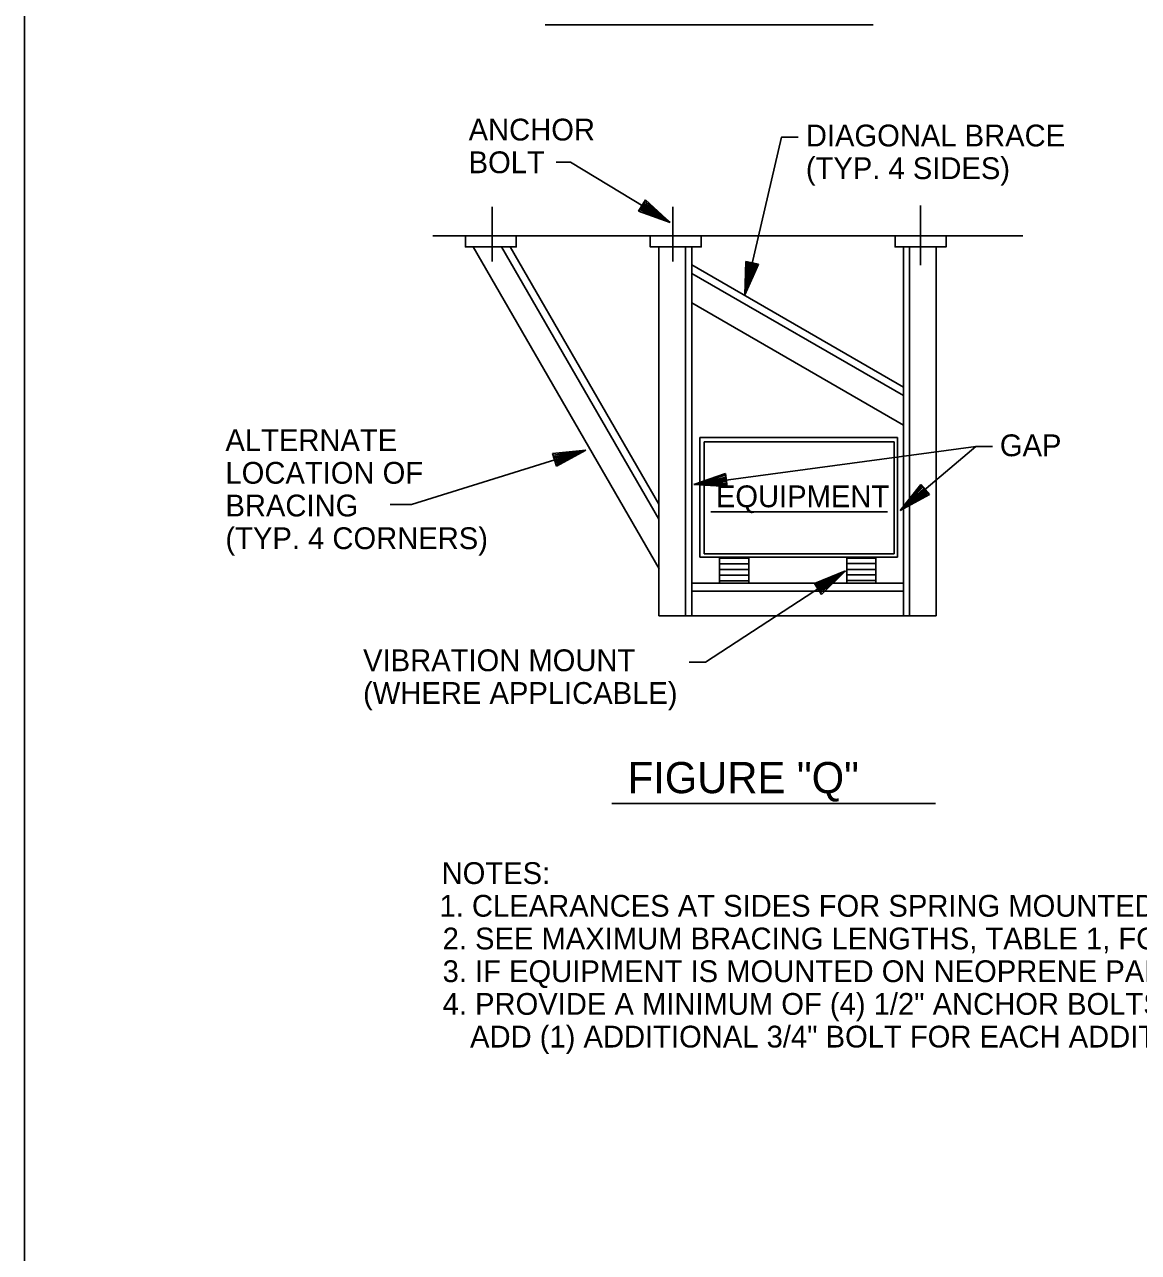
# Model space of a CAD drawing. Extents: x 10040.55 to 10045.84, y 10033.26 to 10035.76.
# Drawn here: x 10042.235 to 10042.746, y 10034.627 to 10035.19 of the extents above; entities that cross this region are included whole.
import ezdxf

# ---------------------------------------------------------------- set-up
doc = ezdxf.new("R2010")
doc.units = 0
doc.layers.add('Level 2', color=7, linetype='Continuous')

msp = doc.modelspace()

# ---------------------------------------------------------------- linework, layer by layer
at = {"layer": 'Level 2'}
for p, q in [((10042.2348, 10035.71385), (10042.2348, 10033.29719)), ((10042.47355, 10035.18978), (10042.62399, 10035.18978)), ((10042.44921, 10035.08122), (10042.44921, 10035.10631)), ((10042.51636, 10035.10443), (10042.5195, 10035.10957)), ((10042.53079, 10035.09918), (10042.51676, 10035.10508)), ((10042.53079, 10035.09918), (10042.51718, 10035.10581)), ((10042.53079, 10035.09918), (10042.51754, 10035.10638)), ((10042.51791, 10035.10698), (10042.53079, 10035.09918)), ((10042.53079, 10035.09918), (10042.5183, 10035.10761)), ((10042.53079, 10035.09918), (10042.51868, 10035.10826)), ((10042.53079, 10035.09918), (10042.51906, 10035.10888)), ((10042.5195, 10035.10957), (10042.53079, 10035.09918)), ((10042.53207, 10035.08122), (10042.53207, 10035.10631)), ((10042.64569, 10035.07959), (10042.64569, 10035.10702)), ((10042.51636, 10035.10443), (10042.53079, 10035.09918)), ((10042.42202, 10035.09301), (10042.69251, 10035.09301)), ((10042.52575, 10034.94035), (10042.44052, 10035.08798)), ((10042.52568, 10034.96305), (10042.45355, 10035.08798)), ((10042.52568, 10034.96995), (10042.45753, 10035.08798)), ((10042.52568, 10034.91869), (10042.52568, 10035.08798)), ((10042.53794, 10035.08798), (10042.53794, 10034.91869)), ((10042.54078, 10034.91869), (10042.54078, 10035.08798)), ((10042.63777, 10035.08798), (10042.63777, 10034.91869)), ((10042.6406, 10034.91869), (10042.6406, 10035.08798)), ((10042.65288, 10035.08798), (10042.65288, 10034.91869)), ((10042.63777, 10035.02368), (10042.54078, 10035.07968)), ((10042.56553, 10035.08135), (10042.56504, 10035.06601)), ((10042.56504, 10035.06601), (10042.56628, 10035.08118)), ((10042.56504, 10035.06601), (10042.5671, 10035.08101)), ((10042.56504, 10035.06601), (10042.56775, 10035.08083)), ((10042.56844, 10035.08069), (10042.56504, 10035.06601)), ((10042.56504, 10035.06601), (10042.56918, 10035.08051)), ((10042.56504, 10035.06601), (10042.56991, 10035.08034)), ((10042.56504, 10035.06601), (10042.5706, 10035.08018)), ((10042.57141, 10035.07998), (10042.56504, 10035.06601)), ((10042.56553, 10035.08135), (10042.57141, 10035.07998)), ((10042.63777, 10035.01983), (10042.54078, 10035.07583)), ((10042.63777, 10035.00624), (10042.54078, 10035.06224)), ((10042.63503, 10035.00058), (10042.54444, 10035.00058)), ((10042.54444, 10034.94568), (10042.54444, 10035.00058)), ((10042.63503, 10034.94568), (10042.63503, 10035.00058)), ((10042.47693, 10034.99319), (10042.49219, 10034.99479)), ((10042.47872, 10034.98743), (10042.47693, 10034.99319)), ((10042.49219, 10034.99479), (10042.47716, 10034.9924)), ((10042.49219, 10034.99479), (10042.47736, 10034.99171)), ((10042.49219, 10034.99479), (10042.4776, 10034.991)), ((10042.47781, 10034.99027), (10042.49219, 10034.99479)), ((10042.49219, 10034.99479), (10042.47803, 10034.9896)), ((10042.49219, 10034.99479), (10042.47822, 10034.98896)), ((10042.49219, 10034.99479), (10042.47849, 10034.98817)), ((10042.47872, 10034.98743), (10042.49219, 10034.99479)), ((10042.55618, 10034.984), (10042.54166, 10034.97902)), ((10042.54166, 10034.97902), (10042.55628, 10034.98324)), ((10042.54166, 10034.97902), (10042.55642, 10034.98241)), ((10042.54166, 10034.97902), (10042.55648, 10034.98174)), ((10042.55658, 10034.98105), (10042.54166, 10034.97902)), ((10042.55618, 10034.984), (10042.55697, 10034.97803)), ((10042.54166, 10034.97902), (10042.55668, 10034.9803)), ((10042.54166, 10034.97902), (10042.55678, 10034.97956)), ((10042.55697, 10034.97803), (10042.54166, 10034.97902)), ((10042.54166, 10034.97902), (10042.55688, 10034.97884)), ((10042.64583, 10034.97906), (10042.63626, 10034.96706)), ((10042.63626, 10034.96706), (10042.64632, 10034.97848)), ((10042.63626, 10034.96706), (10042.64689, 10034.97784)), ((10042.63626, 10034.96706), (10042.6473, 10034.97732)), ((10042.64776, 10034.97679), (10042.63626, 10034.96706)), ((10042.63626, 10034.96706), (10042.64824, 10034.97621)), ((10042.63626, 10034.96706), (10042.64873, 10034.97565)), ((10042.64583, 10034.97906), (10042.64971, 10034.97445)), ((10042.63626, 10034.96706), (10042.64919, 10034.97508)), ((10042.64971, 10034.97445), (10042.63626, 10034.96706)), ((10042.54952, 10034.96642), (10042.63053, 10034.96642)), ((10042.54444, 10034.94568), (10042.63503, 10034.94568)), ((10042.56685, 10034.94515), (10042.55351, 10034.94515)), ((10042.55352, 10034.93382), (10042.55352, 10034.9457)), ((10042.56685, 10034.94258), (10042.55352, 10034.94258)), ((10042.56685, 10034.9457), (10042.56685, 10034.93393)), ((10042.61179, 10034.93382), (10042.61179, 10034.9457)), ((10042.62513, 10034.94524), (10042.61179, 10034.94524)), ((10042.62513, 10034.94268), (10042.61179, 10034.94268)), ((10042.62513, 10034.9457), (10042.62513, 10034.93393)), ((10042.56684, 10034.93999), (10042.55352, 10034.93999)), ((10042.56685, 10034.93743), (10042.55352, 10034.93743)), ((10042.597, 10034.93365), (10042.61125, 10034.93933)), ((10042.61125, 10034.93933), (10042.59744, 10034.93295)), ((10042.61125, 10034.93933), (10042.59782, 10034.93234)), ((10042.61125, 10034.93933), (10042.59824, 10034.93172)), ((10042.59865, 10034.93108), (10042.61125, 10034.93933)), ((10042.61125, 10034.93933), (10042.59904, 10034.9305)), ((10042.61125, 10034.93933), (10042.59939, 10034.92993)), ((10042.61125, 10034.93933), (10042.59986, 10034.92923)), ((10042.60028, 10034.92859), (10042.61125, 10034.93933)), ((10042.62511, 10034.94007), (10042.61178, 10034.94007)), ((10042.61179, 10034.93752), (10042.62513, 10034.93752)), ((10042.63777, 10034.93378), (10042.54078, 10034.93378)), ((10042.56685, 10034.93486), (10042.55352, 10034.93486)), ((10042.60028, 10034.92859), (10042.597, 10034.93365)), ((10042.61178, 10034.93492), (10042.62511, 10034.93492)), ((10042.63777, 10034.93007), (10042.54078, 10034.93007)), ((10042.65288, 10034.91869), (10042.52568, 10034.91869)), ((10042.50415, 10034.83266), (10042.65257, 10034.83266))]:
    msp.add_line(p, q, dxfattribs=at)
for points in [[(10042.58951, 10035.13832), (10042.5819, 10035.13832), (10042.56504, 10035.06601)], [(10042.47859, 10035.12691), (10042.48511, 10035.12691), (10042.53079, 10035.09918)], [(10042.43692, 10035.09301), (10042.43692, 10035.08798), (10042.46025, 10035.08798), (10042.46025, 10035.09301)], [(10042.52173, 10035.09301), (10042.52173, 10035.08798), (10042.54506, 10035.08798), (10042.54506, 10035.09301)], [(10042.634, 10035.09301), (10042.634, 10035.08798), (10042.65733, 10035.08798), (10042.65733, 10035.09301)], [(10042.40248, 10034.96978), (10042.41226, 10034.96978), (10042.49219, 10034.99479)], [(10042.67106, 10034.99642), (10042.54166, 10034.97902)], [(10042.67867, 10034.99642), (10042.67106, 10034.99642), (10042.63626, 10034.96706)], [(10042.53949, 10034.89747), (10042.54709, 10034.89747), (10042.61125, 10034.93933)]]:
    msp.add_lwpolyline(points, dxfattribs=at)
msp.add_lwpolyline([(10042.54648, 10034.94719), (10042.63351, 10034.94719), (10042.63351, 10034.9985), (10042.54648, 10034.9985)], close=True, dxfattribs=at)

# ---------------------------------------------------------------- texts
for s, height, p in [('ANCHOR', 0.01, (10042.43842, 10035.13678)), ('DIAGONAL BRACE', 0.01, (10042.59305, 10035.13407)), ('BOLT', 0.01, (10042.43842, 10035.12178)), ('(TYP. 4 SIDES)', 0.01, (10042.59305, 10035.11907)), ('ALTERNATE', 0.01, (10042.32691, 10034.99434)), ('GAP', 0.01, (10042.68201, 10034.99196)), ('LOCATION OF', 0.01, (10042.32691, 10034.97934)), ('EQUIPMENT', 0.01, (10042.5518, 10034.96856)), ('BRACING', 0.01, (10042.32691, 10034.96434)), ('(TYP. 4 CORNERS)', 0.01, (10042.32691, 10034.94934)), ('VIBRATION MOUNT', 0.01, (10042.39004, 10034.89335)), ('(WHERE APPLICABLE)', 0.01, (10042.39004, 10034.87835)), ('FIGURE "Q"', 0.014301, (10042.51138, 10034.83739)), ('NOTES:', 0.01, (10042.42603, 10034.79573)), ('1. CLEARANCES AT SIDES FOR SPRING MOUNTED EQUIPMENT AS IN FIG. "R" & "S", SHALL BE IN ACCORDANCE WITH MFR\'S. RECOMMENDATIONS.', 0.01, (10042.42507, 10034.78073)), ('2. SEE MAXIMUM BRACING LENGTHS, TABLE 1, FOR BRACE SIZES.', 0.01, (10042.4265, 10034.76573)), ('3. IF EQUIPMENT IS MOUNTED ON NEOPRENE PADS, ANCHOR BOLTS SHALL BE ISOLATED FROM EQUIPMENT BY A NEOPRENE SLEEVE AND WASHER.', 0.01, (10042.4265, 10034.75073)), ('4. PROVIDE A MINIMUM OF (4) 1/2" ANCHOR BOLTS FOR EQUIPMENT UP TO 10,000 LBS. AND (4) 3/4" BOLTS FOR EQUIPMENT 10,000 LBS. OR GREATER.', 0.01, (10042.4265, 10034.73573)), ('   ADD (1) ADDITIONAL 3/4" BOLT FOR EACH ADDITIONAL 2,500 LBS.', 0.01, (10042.42794, 10034.72073))]:
    msp.add_text(s, height=height, dxfattribs=at).set_placement(p)

doc.saveas('drawing.dxf')
